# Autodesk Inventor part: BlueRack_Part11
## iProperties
Shininess: 64.0
Length Units: 11272
Angle Units: 11279
Time Units: 11290
Mass Units: 11286
Length Display Precision: 3
Angle Display Precision: 2
Compacted: True
Part Number: BlueRack_Part11
Document SubType Name: Modeling
Created: 2004-12
Designer: John Blackburn
Material: Steel, Mild
Manufacturer: Standard
Standards Organization: Custom
Density: 0.0
Volumn: 0.0
Area: 0.0
PropertySet Name: Model Information
Control State: 0
Master: False
Checked Out: False
Author: John Blackburn
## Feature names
1. Extrusion1
2. Extrusion2
3. Extrusion3
4. Fillet1
5. Fillet2
